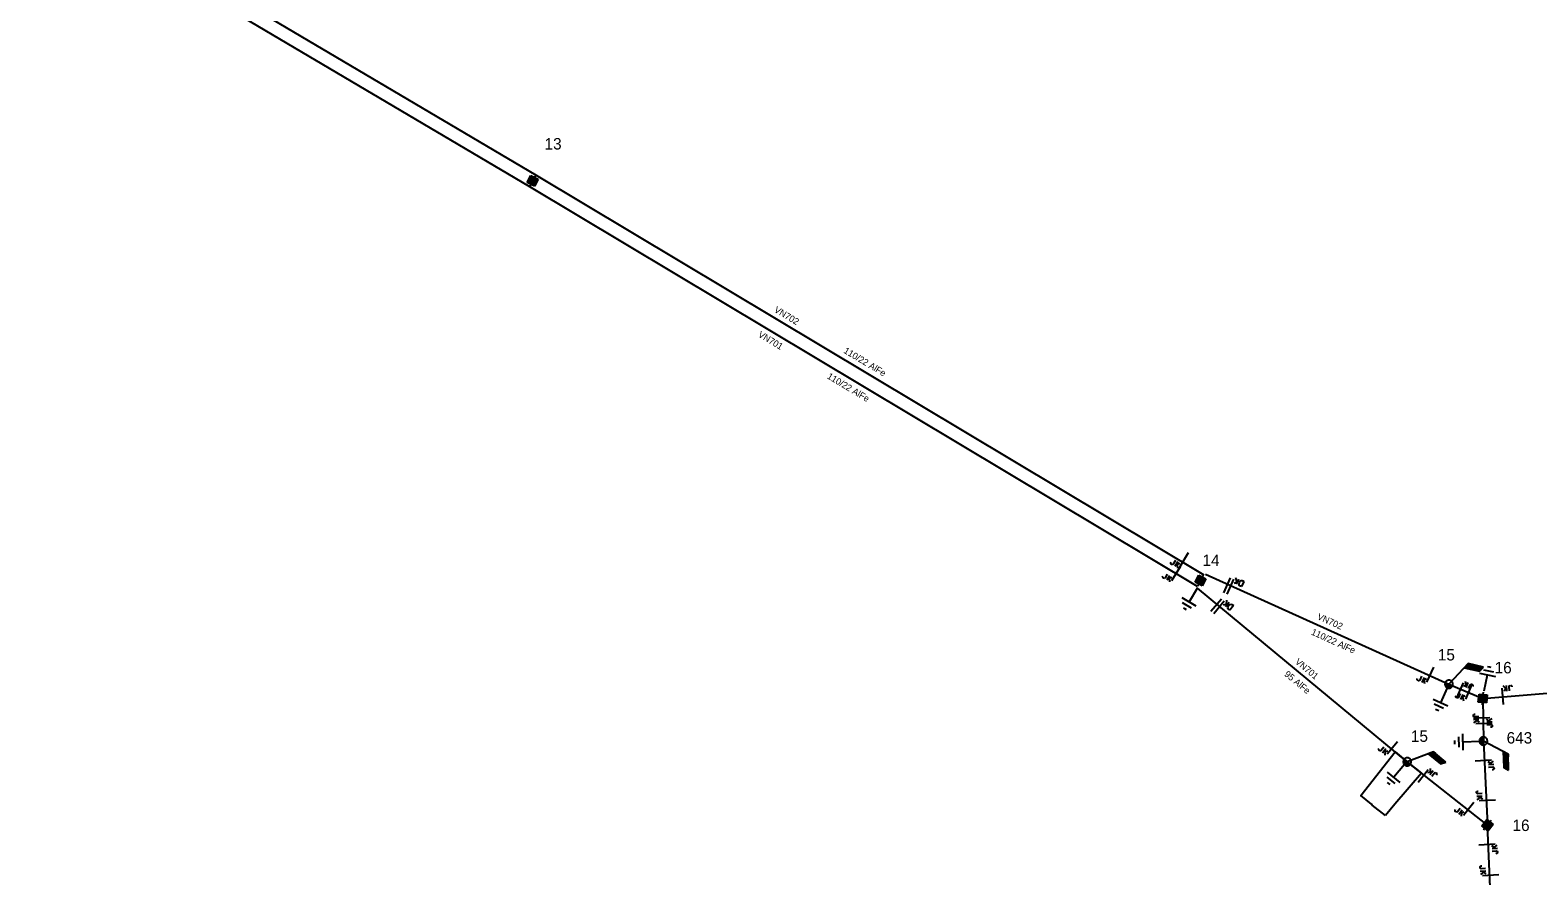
# Model space of a CAD drawing. Extents: x -545588 to -543214, y -1196037 to -1194452.
# Drawn here: x -543827.7 to -543597.4, y -1195898.4 to -1195769.2 of the extents above; entities that cross this region are included whole.
import ezdxf

# ---------------------------------------------------------------- set-up
doc = ezdxf.new("R2010")
doc.units = 0
for name, color, linetype in [('DOPLŇ_POPISY', 7, 'Continuous'), ('ELE_EON', 7, 'Continuous'), ('ELE_EON_POPIS', 7, 'Continuous'), ('Implicitní', 7, 'Continuous'), ('POL_ZNAČKA_PRACOVNÍ', 7, 'Continuous'), ('SDEL_EON', 7, 'Continuous'), ('TECH_OCHR_PÁSMO_HRAN', 7, 'Continuous'), ('Vrstva 18', 7, 'Continuous'), ('Vrstva 35', 7, 'Continuous'), ('Vrstva 52', 7, 'Continuous')]:
    doc.layers.add(name, color=color, linetype=linetype)

# ---------------------------------------------------------------- blocks, each defined once
blk = doc.blocks.new('VN850')
at = {"layer": 'POL_ZNAČKA_PRACOVNÍ'}
for points in [[(-0.56, 1.43), (-0.56, -1.07)], [(-0.01, 1.43), (-0.01, -1.07)], [(-2.09, -0.54), (-1.78, -0.54)], [(-2.09, -1.41), (-2.09, -0.54)], [(-1.78, -1.41), (-2.09, -1.41)], [(-1.78, -0.54), (-1.66, -0.6)], [(-1.67, -1.35), (-1.78, -1.41)], [(-1.59, -1.2), (-1.67, -1.35)], [(-1.66, -0.6), (-1.59, -0.75)], [(-1.59, -0.75), (-1.55, -0.96)], [(-1.55, -0.96), (-1.59, -1.2)], [(-1.26, -0.54), (-1.26, -1.41)], [(-0.85, -0.54), (-1.26, -1.09)], [(-1.13, -0.92), (-0.77, -1.41)]]:
    blk.add_lwpolyline(points, dxfattribs=at)
blk = doc.blocks.new('VN840')
at = {"layer": 'POL_ZNAČKA_PRACOVNÍ'}
for points in [[(-0.01, 1.41), (-0.01, -1.09)], [(-1.51, -1.24), (-1.51, -1.15)], [(-1.48, -1.35), (-1.51, -1.24)], [(-1.33, -1.42), (-1.48, -1.35)], [(-1.27, -1.42), (-1.33, -1.42)], [(-1.13, -1.35), (-1.27, -1.42)], [(-1.09, -1.24), (-1.13, -1.35)], [(-1.09, -0.59), (-1.09, -1.24)], [(-0.68, -0.59), (-0.68, -1.42)], [(-0.68, -1.11), (-0.27, -0.59)], [(-0.54, -0.94), (-0.2, -1.42)]]:
    blk.add_lwpolyline(points, dxfattribs=at)
blk = doc.blocks.new('VN440')
at = {"layer": 'ELE_EON_POPIS'}
for points in [[(1.22, 0), (1.21, 0.13), (1.19, 0.25), (1.16, 0.38), (1.11, 0.5), (1.05, 0.61), (0.98, 0.72), (0.9, 0.82), (0.81, 0.91), (0.71, 0.99), (0.6, 1.06), (0.49, 1.12), (0.37, 1.16), (0.25, 1.2), (0.12, 1.22), (-0.01, 1.22), (-0.14, 1.22), (-0.26, 1.2), (-0.39, 1.16), (-0.51, 1.12), (-0.62, 1.06), (-0.73, 0.99), (-0.83, 0.91), (-0.92, 0.82), (-1, 0.72), (-1.07, 0.61), (-1.13, 0.5), (-1.18, 0.38), (-1.21, 0.25), (-1.23, 0.13), (-1.24, 0), (-1.23, -0.13), (-1.21, -0.26), (-1.18, -0.38), (-1.13, -0.5), (-1.07, -0.62), (-1, -0.73), (-0.92, -0.83), (-0.83, -0.92), (-0.73, -1), (-0.62, -1.07), (-0.51, -1.13), (-0.39, -1.17), (-0.26, -1.2), (-0.14, -1.23), (-0.01, -1.23), (0.12, -1.23), (0.25, -1.2), (0.37, -1.17), (0.49, -1.13), (0.6, -1.07), (0.71, -1), (0.81, -0.92), (0.9, -0.83), (0.98, -0.73), (1.05, -0.62), (1.11, -0.5), (1.16, -0.38), (1.19, -0.26), (1.21, -0.13), (1.22, 0)], [(-1.24, 0), (1.22, 0)], [(-1.18, -0.34), (1.1, -0.34)], [(-1.01, -0.63), (0.97, -0.63)], [(-0.74, -0.92), (0.68, -0.92)]]:
    blk.add_lwpolyline(points, dxfattribs=at)
blk = doc.blocks.new('VN810')
at = {"layer": 'POL_ZNAČKA_PRACOVNÍ'}
for points in [[(0, -1.25), (0, -3.75)], [(1.25, -3.75), (-1.25, -3.75)], [(0.77, -4.37), (-0.8, -4.37)], [(0, -5), (-0.25, -5)], [(0.27, -5), (0, -5)]]:
    blk.add_lwpolyline(points, dxfattribs=at)
blk = doc.blocks.new('VN001')
at = {"layer": 'Implicitní'}
for p, q in [((1.73, 3.03), (4.14, 3.03)), ((1.76, 3.08), (4.17, 3.08)), ((1.79, 3.13), (4.2, 3.13)), ((1.82, 3.18), (4.23, 3.18)), ((1.85, 3.23), (4.26, 3.23)), ((1.87, 3.28), (4.29, 3.28)), ((1.9, 3.33), (4.32, 3.33)), ((1.93, 3.38), (4.35, 3.38)), ((1.96, 3.43), (4.37, 3.43)), ((1.99, 3.48), (4.4, 3.48)), ((2.02, 3.53), (4.43, 3.53)), ((2.05, 3.58), (4.46, 3.58)), ((2.07, 3.63), (4.49, 3.63)), ((2.1, 3.68), (4.52, 3.68)), ((2.13, 3.73), (2.54, 3.73))]:
    blk.add_line(p, q, dxfattribs=at)
blk.add_lwpolyline([(2.13, 3.73), (0, 0)], dxfattribs=at)
blk.add_lwpolyline([(4.55, 3.73), (2.13, 3.73), (1.7, 2.98), (4.12, 2.99)], close=True, dxfattribs=at)
blk = doc.blocks.new('VN470')
at = {"layer": 'ELE_EON_POPIS'}
for points in [[(-1.23, 1.22), (1.23, 1.22)], [(-1.23, -1.23), (-1.23, 1.22)], [(-0.92, 0.9), (0.92, 0.9)], [(-0.92, -0.95), (-0.92, 0.9)], [(-0.61, 0.61), (0.61, 0.61)], [(-0.61, -0.62), (-0.61, 0.61)], [(-0.31, -0.27), (-0.31, 0.34)], [(-0.31, 0.34), (0.31, 0.34)], [(0, 1.22), (0, 1.97)], [(0.31, 0.34), (0.31, -0.27)], [(0.61, 0.61), (0.61, -0.62)], [(0.92, 0.9), (0.92, -0.95)], [(1.23, 1.22), (1.23, -1.23)], [(1.23, -1.23), (-1.23, -1.23)], [(0.92, -0.95), (-0.92, -0.95)], [(0.61, -0.62), (-0.61, -0.62)], [(0.31, -0.27), (-0.31, -0.27)], [(0, -1.23), (0, -1.98)]]:
    blk.add_lwpolyline(points, dxfattribs=at)

msp = doc.modelspace()

# ---------------------------------------------------------------- linework, layer by layer
at = {"layer": 'ELE_EON'}
for points in [[(-543605.83, -1195871.31), (-543527.67, -1195864.84), (-543432.77, -1195857.32), (-543323.46, -1195848.64), (-543214.01, -1195839.86)], [(-543648.17, -1195852.31), (-543611, -1195869.14)], [(-543617.36, -1195881), (-543649.39, -1195854.44)], [(-543611, -1195869.14), (-543605.83, -1195871.31)], [(-543605.11, -1195890.68), (-543617.36, -1195881)], [(-543604.63, -1195901.33), (-543605.11, -1195890.68)]]:
    msp.add_lwpolyline(points, dxfattribs=at)
at = {"layer": 'Implicitní'}
for points in [[(-545087.92, -1194964.41), (-544969.06, -1195068.81), (-544833.21, -1195149.88), (-544688.64, -1195235.58), (-544556.54, -1195314.1), (-544420.62, -1195395.04), (-544280.05, -1195478.05), (-544140.98, -1195560.03), (-544005.82, -1195639.79), (-543873.77, -1195718.4), (-543750.46, -1195791.32), (-543648.45, -1195852.42)], [(-545089.24, -1194965.91), (-544970.24, -1195070.43), (-544834.23, -1195151.6), (-544689.66, -1195237.3), (-544557.56, -1195315.82), (-544421.64, -1195396.76), (-544281.07, -1195479.77), (-544142, -1195561.75), (-544006.84, -1195641.51), (-543874.79, -1195720.12), (-543751.48, -1195793.04), (-543649.47, -1195854.14)]]:
    msp.add_lwpolyline(points, dxfattribs=at)
at = {"layer": 'Vrstva 35'}
msp.add_lwpolyline([(-543620.7, -1195889.19), (-543622.71, -1195887.61), (-543622.84, -1195887.5), (-543624.45, -1195886.17), (-543619.23, -1195879.45), (-543617.36, -1195881), (-543615.19, -1195882.72), (-543619.26, -1195887.5)], close=True, dxfattribs=at)
at = {"layer": 'Vrstva 52'}
for points in [[(-543605.83, -1195871.31), (-543605.73, -1195877.83)], [(-543605.73, -1195877.83), (-543605.11, -1195890.68)]]:
    msp.add_lwpolyline(points, dxfattribs=at)

# ---------------------------------------------------------------- block references
at = {"layer": 'DOPLŇ_POPISY'}
for name, p, xscale, yscale, rotation in [('VN470', (-543750.97, -1195792.18), 0.4999999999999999, 0.5000000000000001, 152.25449483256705), ('VN470', (-543648.96, -1195853.28), 0.4999999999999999, 0.5000000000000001, -27.20396481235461), ('VN440', (-543610.99, -1195869.14), 0.5, 0.5, -24.396491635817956), ('VN470', (-543605.83, -1195871.31), 0.4999999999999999, 0.5000000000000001, -5.936005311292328), ('VN440', (-543605.73, -1195877.83), 0.49999999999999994, 0.5, -88.40873060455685), ('VN440', (-543617.36, -1195881), 0.5, 0.5, -39.67067774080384), ('VN470', (-543605.11, -1195890.68), 0.49999999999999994, 0.5000000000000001, -38.31669718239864)]:
    msp.add_blockref(name, p, dxfattribs=dict(at, xscale=xscale, yscale=yscale, rotation=rotation))
at = {"layer": 'POL_ZNAČKA_PRACOVNÍ'}
for p, rotation in [((-543648.75, -1195853.35), -30.983391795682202), ((-543605.91, -1195871.36), 167.3754416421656), ((-543610.74, -1195868.56), -24.396991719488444), ((-543605.09, -1195877.87), -88.40952778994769), ((-543617.01, -1195880.47), -39.6711138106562)]:
    msp.add_blockref('VN810', p, dxfattribs=dict(at, rotation=rotation))
at = {"layer": 'TECH_OCHR_PÁSMO_HRAN'}
for p, rotation in [((-543611, -1195869.14), -13.05202785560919), ((-543617.36, -1195881), -39.670955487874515), ((-543605.73, -1195877.83), -88.40301664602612)]:
    msp.add_blockref('VN001', p, dxfattribs=dict(at, rotation=rotation))
at = {"layer": 'Vrstva 18'}
for name, p, rotation in [('VN840', (-543651.55, -1195850.29), -31.001511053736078), ('VN840', (-543652.79, -1195852.39), -31.001511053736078), ('VN850', (-543644.81, -1195853.84), 155.60301665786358), ('VN850', (-543646.44, -1195856.88), 140.32877214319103), ('VN840', (-543613.94, -1195867.84), -24.39698334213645), ('VN840', (-543608.04, -1195870.44), -23.252591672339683), ('VN840', (-543609.23, -1195869.93), 156.74740832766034), ('VN840', (-543602.79, -1195870.83), -175.44626947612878), ('VN840', (-543605.8, -1195875.2), -88.40066669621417), ('VN840', (-543605.83, -1195874.24), 91.59023606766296), ('VN840', (-543619.74, -1195879.02), -39.67122785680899), ('VN840', (-543605.59, -1195880.76), 92.76232223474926), ('VN840', (-543614.83, -1195883), 141.6840666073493), ('VN840', (-543605.29, -1195886.93), -87.23767776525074), ('VN840', (-543608.07, -1195888.34), -38.315933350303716), ('VN840', (-543605.03, -1195893.59), 92.7108445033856), ('VN840', (-543604.76, -1195898.37), -87.42202774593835)]:
    msp.add_blockref(name, p, dxfattribs=dict(at, rotation=rotation))

# ---------------------------------------------------------------- texts
at = {"layer": 'ELE_EON_POPIS'}
for s, rotation, p in [('110/22 AlFe', 328.998, (-543703.56, -1195818.42)), ('110/22 AlFe', 329.037, (-543706.09, -1195822.33)), ('110/22 AlFe', 335.603, (-543632.13, -1195861.51)), ('95 AlFe', 320.329, (-543636.23, -1195867.76))]:
    msp.add_text(s, height=1, rotation=rotation, dxfattribs=at).set_placement(p)
at = {"layer": 'POL_ZNAČKA_PRACOVNÍ'}
for s, p in [('13', (-543749.15, -1195787.4)), ('14', (-543648.64, -1195851.07)), ('15', (-543612.69, -1195865.51)), ('16', (-543604.01, -1195867.48)), ('15', (-543616.8, -1195877.95)), ('643', (-543602.18, -1195878.21)), ('16', (-543601.28, -1195891.58))]:
    msp.add_text(s, height=1.75, dxfattribs=at).set_placement(p)
at = {"layer": 'SDEL_EON'}
for s, rotation, p in [('VN702', 328.998, (-543714.17, -1195812.17)), ('VN701', 329.037, (-543716.62, -1195815.96)), ('VN702', 335.603, (-543631.22, -1195859.15)), ('VN701', 320.329, (-543634.59, -1195865.87))]:
    msp.add_text(s, height=1, rotation=rotation, dxfattribs=at).set_placement(p)

doc.saveas('drawing.dxf')
